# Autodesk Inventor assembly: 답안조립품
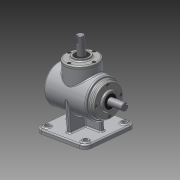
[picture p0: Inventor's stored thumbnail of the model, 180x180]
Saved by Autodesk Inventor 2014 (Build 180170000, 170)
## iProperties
Created: 2015-07
Part Number: 답안조립품
Document SubType Name: Assembly
Designer: net
Author: net
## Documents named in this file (14)
- C:\Users\net\Desktop\450705V1017\답안조립품.iam
- C:\Users\net\Desktop\450705V1017\본체.ipt
- C:\Users\net\Desktop\450705V1017\커버.ipt
- C:\Users\net\Desktop\450705V1017\베어링 6203.ipt
- C:\Users\net\Desktop\450705V1017\메인 축.ipt
- 메인 축.ipt
- C:\Users\net\Desktop\450705V1017\키 5x5.ipt
- C:\Users\net\Desktop\450705V1017\메인 베벨기어.ipt
- C:\Users\net\Desktop\450705V1017\서브 축.ipt
- 서브 축.ipt
- C:\Users\net\Desktop\450705V1017\키 4x4.ipt
- C:\Users\net\Desktop\450705V1017\서브 베벨기어.ipt
- C:\Users\net\Desktop\450705V1017\오일실.ipt
- C:\Users\net\Desktop\450705V1017\M4.ipt
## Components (8 placed, 1 different names)
1. M4:1
2. M4:2
3. M4:3
4. M4:4
5. M4:5
6. M4:6
7. M4:7
8. M4:8
